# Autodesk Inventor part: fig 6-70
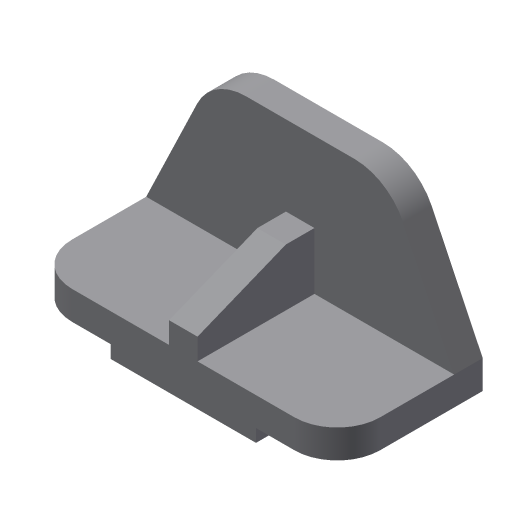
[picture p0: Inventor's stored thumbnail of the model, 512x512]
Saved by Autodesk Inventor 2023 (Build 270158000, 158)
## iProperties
Created: 2001-12
Part Number: fig 6-70
Document SubType Name: Modeling
Designer: Renu Muthoo
Density: 1 g/cm^3
Material: Generic
Appearance: Default
Control State: 0
Master: False
Checked Out: False
Shininess: 77.0
Length Units: 11269
Angle Units: 11279
Time Units: 11290
Mass Units: 11283
Length Display Precision: 3
Angle Display Precision: 2
Density: 0.0
Volumn: 0.0
Area: 0.0
PropertySet Name: Model Information
Author: Renu Muthoo
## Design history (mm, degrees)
sketch "Sketch2"
  geometry: L1 (-67.219, 19.116)-(148.781, 19.116); L2 (148.781, 19.116)-(148.781, -0.884); L3 (-67.219, -0.884)-(-67.219, 19.116); L4 (-10.219, -0.884)-(-10.219, -9.884); L5 (-10.219, -9.884)-(91.781, -9.884); L6 (91.781, -9.884)-(91.781, -0.884); L7 (148.781, -0.884)-(91.781, -0.884); L8 (-10.219, -0.884)-(-67.219, -0.884)
  constraints: 16 end point, 5 parallel, 4 perpendicular, 2 equal length, 1 horizontal
  dimensions: "d0" = 102 distance of L4.end L5.end; "d1" = 57 distance of L4.start L3.start; "d2" = 29 distance between parallel lines of L1 L5; "d3" = 20 distance of L1.end L2.end
extrude "Extrusion1" new body sketch "Sketch2" distance "d4" = 102; taper "d5" = 0 deg
sketch "Sketch3"
  geometry: L1 (67.219, -19.116)-(-148.781, -19.116) reference; L2 (67.219, -19.116)-(31.475, -93.564); L3 (-2.781, -115.116)-(-78.781, -115.116); L4 (-113.038, -93.564)-(-148.781, -19.116); A1 r 38 centre (-2.781, -77.116) between (-2.781, -115.116) and (31.475, -93.564); A2 r 38 centre (-78.781, -77.116) between (-113.038, -93.564) and (-78.781, -115.116)
  constraints: 6 end point, 4 point on circle, 4 tangent, 2 centre point, 1 equal length, 1 equal radius, 1 parallel
  dimensions: "d6" = 96 distance between parallel lines of L3 L1; "d7" = 38 radius of A1; "d8" = 76 distance of A2.centre A1.centre
extrude "Extrusion2" join sketch "Sketch3" distance "d9" = 20; taper "d10" = 0 deg
fillet "Fillet1" dims "d11" = 30
workplane "Work Plane1"
sketch "Sketch7"
  geometry: L1 (0, -82)-(-15, -82); L2 (-15, -82)-(-40, -20); L3 (-40, -20)-(-40, 0); L4 (0, -82)-(20, -82) reference; L5 (0, 0)-(-74.447, 0) reference
  constraints: 6 end point, 2 point on line, 1 horizontal, 1 perpendicular
  dimensions: "d32" = 20 distance of L2.end L3.end; "d33" = 15 distance of L1.start L1.end; "d34" = 40 distance of L5.start L3.end
feature "Rib4" sketch "Sketch7" dims "d55" = 1, "d56" = 20, "d57" = 0
body "Solid1"
other parameters: "d12" = -108
